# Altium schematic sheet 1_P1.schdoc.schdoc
size 309 x 223 mm; Symbol: Sheet-Symbol_A4; Device: Sheet-Symbol_A4; Company: A. ROMASZEWSKI; Drawed: EasyEDA Pro; Reviewed: EasyEDA Pro; Version: V0.1; Page Size: A4; @Project Name: stm32wb5mmg01; @Page Count: 1; @Update Date: 2023-12-18; @Create Date: 2023-10-27; @Schematic Name: Shield stm32wb5mm-dk; Part Number: SHMMDK-002; @Page No: 1; @Page Name: P1; attr-text: ADS1115 ADR I2C 0x76
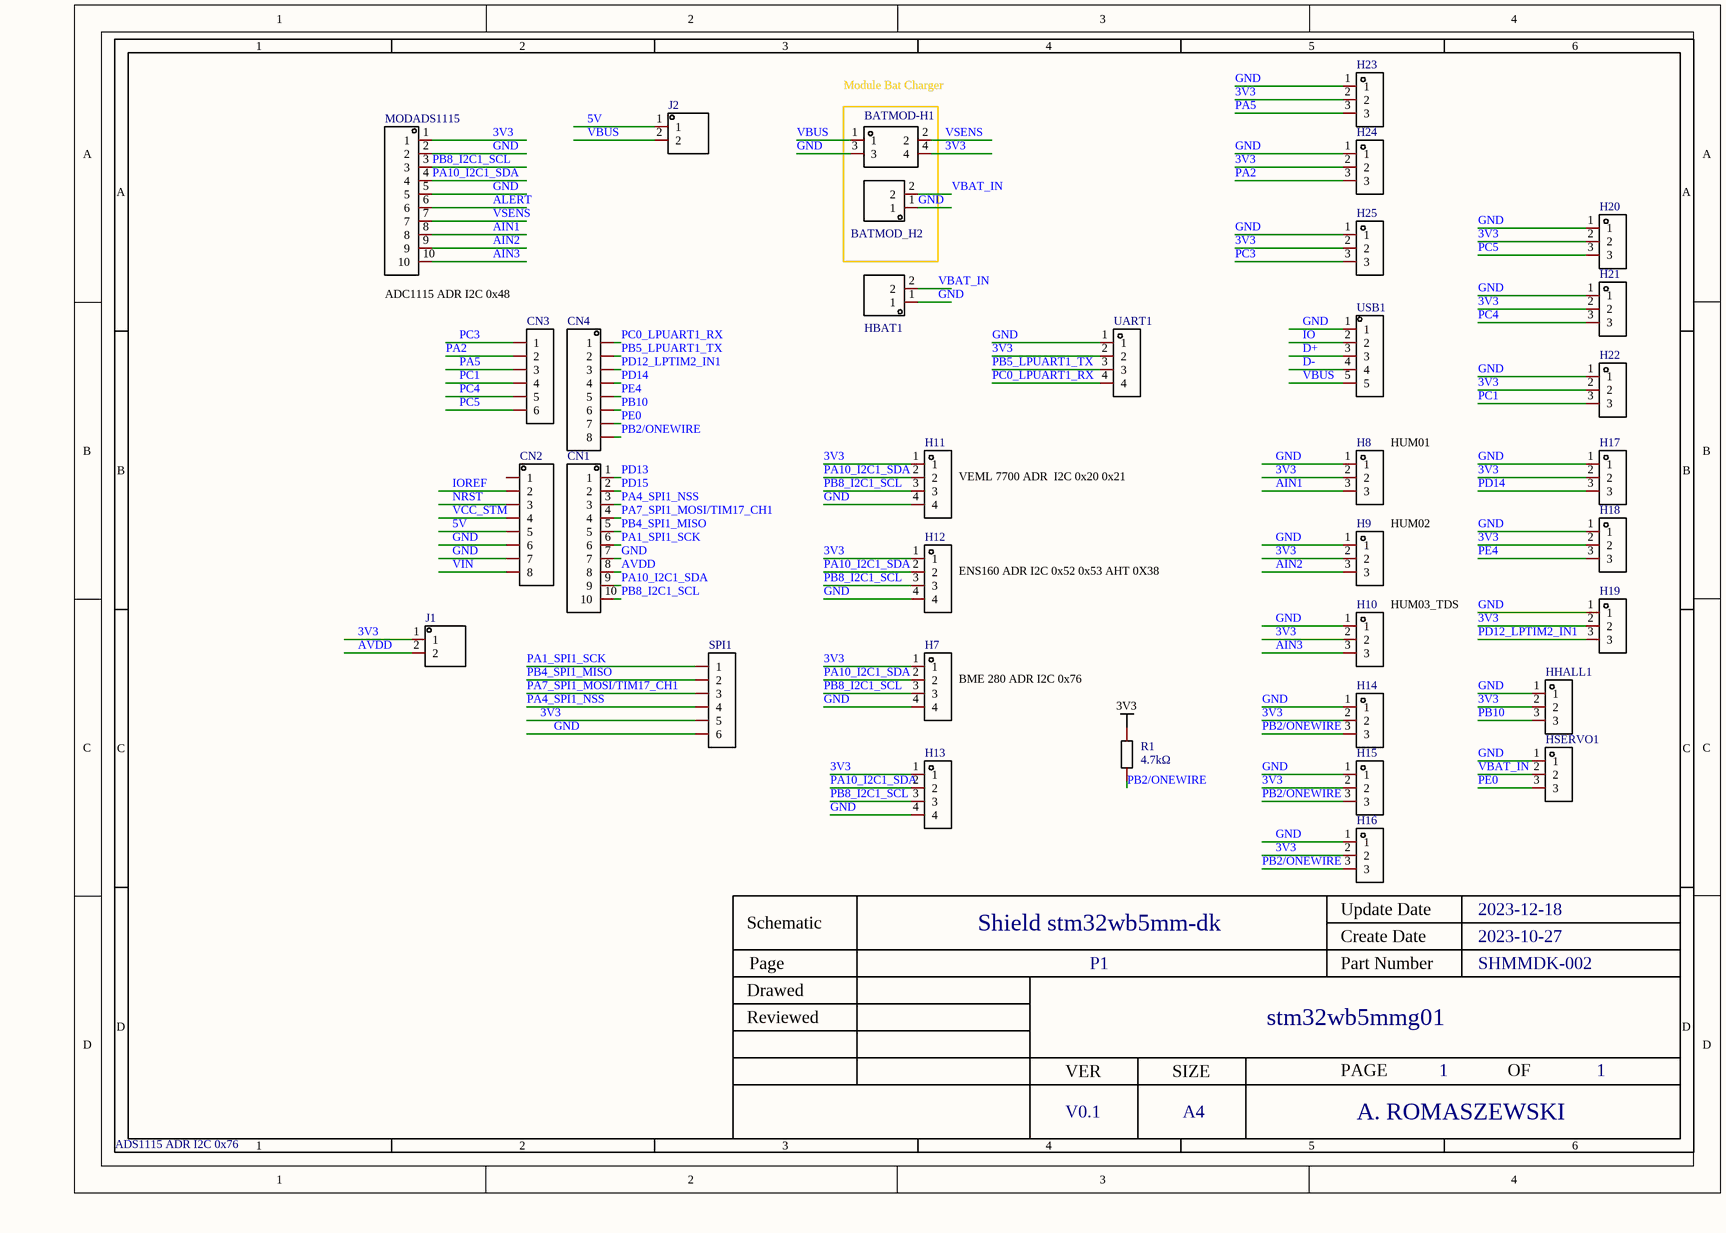
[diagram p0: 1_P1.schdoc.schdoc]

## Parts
BATMOD-H1  HDR-M_2.54_2x2  [HDR-TH_4P-P2.54-V-M-R2-C2-S2.54-1]  (value not drawn)
BATMOD_H2  HDR-M_2.54_1x2P  [HDR-TH_2P-P2.54-V-M-1]  (value not drawn)
CN1  HDR-M_2.54_1x10P  [HDR-TH_10P-P2.54-V-M-1]  (value not drawn)
CN2  HDR-M_2.54_1x8P  [HDR-TH_8P-P2.54-V-M]  (value not drawn)
CN3  HDR-M_2.54_1x6P  [HDR-TH_6P-P2.54-V-M-1]  (value not drawn)
CN4  HDR-M_2.54_1x8P  [HDR-TH_8P-P2.54-V-M]  (value not drawn)
H7  HDR-M_2.54_1x4P  [HDR-TH_4P-P2.54-V-M]  (value not drawn)
H8  HDR-M_2.54_1x3P  [HDR-TH_3P-P2.54-V-M]  (value not drawn)
H9  HDR-M_2.54_1x3P  [HDR-TH_3P-P2.54-V-M]  (value not drawn)
H10  HDR-M_2.54_1x3P  [HDR-TH_3P-P2.54-V-M]  (value not drawn)
H11  HDR-M_2.54_1x4P  [HDR-TH_4P-P2.54-V-M]  (value not drawn)
H12  HDR-M_2.54_1x4P  [HDR-TH_4P-P2.54-V-M]  (value not drawn)
H13  HDR-M_2.54_1x4P  [HDR-TH_4P-P2.54-V-M]  (value not drawn)
H14  HDR-M_2.54_1x3P  [HDR-TH_3P-P2.54-V-M]  (value not drawn)
H15  HDR-M_2.54_1x3P  [HDR-TH_3P-P2.54-V-M]  (value not drawn)
H16  HDR-M_2.54_1x3P  [HDR-TH_3P-P2.54-V-M]  (value not drawn)
H17  HDR-M_2.54_1x3P  [HDR-TH_3P-P2.54-V-M]  (value not drawn)
H18  HDR-M_2.54_1x3P  [HDR-TH_3P-P2.54-V-M]  (value not drawn)
H19  HDR-M_2.54_1x3P  [HDR-TH_3P-P2.54-V-M]  (value not drawn)
H20  HDR-M_2.54_1x3P  [HDR-TH_3P-P2.54-V-M]  (value not drawn)
H21  HDR-M_2.54_1x3P  [HDR-TH_3P-P2.54-V-M]  (value not drawn)
H22  HDR-M_2.54_1x3P  [HDR-TH_3P-P2.54-V-M]  (value not drawn)
H23  HDR-M_2.54_1x3P  [HDR-TH_3P-P2.54-V-M]  (value not drawn)
H24  HDR-M_2.54_1x3P  [HDR-TH_3P-P2.54-V-M]  (value not drawn)
H25  HDR-M_2.54_1x3P  [HDR-TH_3P-P2.54-V-M]  (value not drawn)
HBAT1  HDR-M_2.54_1x2P  [HDR-TH_2P-P2.54-V-M-1]  (value not drawn)
HHALL1  HDR-M_2.54_1x3P  [HDR-TH_3P-P2.54-V-M]  (value not drawn)
HSERVO1  HDR-M_2.54_1x3P  [HDR-TH_3P-P2.54-V-M]  (value not drawn)
J1  HDR-M_2.54_1x2P  [HDR-TH_2P-P2.54-V-M-1]  (value not drawn)
J2  HDR-M_2.54_1x2P  [HDR-TH_2P-P2.54-V-M-1]  (value not drawn)
MODADS1115  HDR-M_2.54_1x10P  [HDR-TH_10P-P2.54-V-M-1]  (value not drawn)
R1  4.7kΩ  [R1206]
SPI1  HDR-M_2.54_1x6P  [HDR-TH_6P-P2.54-V-M-1]  (value not drawn)
UART1  HDR-M_2.54_1x4P  [HDR-TH_4P-P2.54-V-M]  (value not drawn)
USB1  HDR-M_2.54_1x5P  [HDR-TH_5P-P2.54-V-M]  (value not drawn)

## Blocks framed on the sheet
Module Bat Charger: BATMOD-H1 BATMOD_H2

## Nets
3V3: BATMOD-H1.4 H7.1 H8.2 H9.2 H10.2 H11.1 H12.1 H13.1 H14.2 H15.2 H16.2 H17.2 H18.2 H19.2 H20.2 H21.2 H22.2 H23.2 H24.2 H25.2 HHALL1.2 J1.1 MODADS1115.1 R1.2 SPI1.5 UART1.2
5V: CN2.5 J2.1
AIN1: H8.3 MODADS1115.8
AIN2: H9.3 MODADS1115.9
AIN3: H10.3 MODADS1115.10
ALERT: MODADS1115.6
AVDD: CN1.8 J1.2
D+: USB1.3
D-: USB1.4
GND: BATMOD-H1.3 BATMOD_H2.1 CN1.7 CN2.6 CN2.7 H7.4 H8.1 H9.1 H10.1 H11.4 H12.4 H13.4 H14.1 H15.1 H16.1 H17.1 H18.1 H19.1 H20.1 H21.1 H22.1 H23.1 H24.1 H25.1 HBAT1.1 HHALL1.1 HSERVO1.1 MODADS1115.2 MODADS1115.5 SPI1.6 UART1.1 USB1.1
IO: USB1.2
IOREF: CN2.2
NRST: CN2.3
PA1_SPI1_SCK: CN1.6 SPI1.1
PA2: CN3.2 H24.3
PA4_SPI1_NSS: CN1.3 SPI1.4
PA5: CN3.3 H23.3
PA7_SPI1_MOSI/TIM17_CH1: CN1.4 SPI1.3
PA10_I2C1_SDA: CN1.9 H7.2 H11.2 H12.2 H13.2 MODADS1115.4
PB2/ONEWIRE: CN4.8 H14.3 H15.3 H16.3 R1.1
PB4_SPI1_MISO: CN1.5 SPI1.2
PB5_LPUART1_TX: CN4.2 UART1.3
PB8_I2C1_SCL: CN1.10 H7.3 H11.3 H12.3 H13.3 MODADS1115.3
PB10: CN4.6 HHALL1.3
PC0_LPUART1_RX: CN4.1 UART1.4
PC1: CN3.4 H22.3
PC3: CN3.1 H25.3
PC4: CN3.5 H21.3
PC5: CN3.6 H20.3
PD12_LPTIM2_IN1: CN4.3 H19.3
PD13: CN1.1
PD14: CN4.4 H17.3
PD15: CN1.2
PE0: CN4.7 HSERVO1.3
PE4: CN4.5 H18.3
VBAT_IN: BATMOD_H2.2 HBAT1.2 HSERVO1.2
VBUS: BATMOD-H1.1 J2.2 USB1.5
VCC_STM: CN2.4
VIN: CN2.8
VSENS: BATMOD-H1.2 MODADS1115.7

Not connected (* = marked no-connect by the designer): CN2 1

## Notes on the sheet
- (near MODADS1115) ADC1115 ADR I2C 0x48
- (near H8) HUM01
- (near H11) VEML 7700 ADR  I2C 0x20 0x21
- HUM02
- (near H12) ENS160 ADR I2C 0x52 0x53 AHT 0X38
- HUM03_TDS
- (near H7) BME 280 ADR I2C 0x76

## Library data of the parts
BATMOD-H1 = HDR-M_2.54_2x2: Symbol: HDR-M-2.54_2x2; Add into BOM: no; Convert to PCB: yes
BATMOD_H2 HBAT1 J1 J2 = HDR-M_2.54_1x2P: Symbol: 210S-1*2P L=11.6MMGold-plated black; Convert to PCB: yes; Add into BOM: no
CN1 MODADS1115 = HDR-M_2.54_1x10P: Symbol: Header-Male-2.54_1x10; Convert to PCB: yes; Add into BOM: no
CN2 CN4 = HDR-M_2.54_1x8P: Symbol: Header-Male-2.54_1x8; Convert to PCB: yes; Add into BOM: no
CN3 SPI1 = HDR-M_2.54_1x6P: Symbol: Header-Male-2.54_1x6; Convert to PCB: yes; Add into BOM: no
H7 H11-H13 UART1 = HDR-M_2.54_1x4P: Manufacturer: XFCN(兴飞); Symbol: PZ254V-11-04P; Convert to PCB: yes; Add into BOM: no
H8-H10 H14-H25 HHALL1 HSERVO1 = HDR-M_2.54_1x3P: Symbol: PZ254V-11-03P_C2937625; Convert to PCB: yes; Add into BOM: no
R1 = Res_1206: Symbol: Res; Add into BOM: no; Convert to PCB: yes
USB1 = HDR-M_2.54_1x5P: Symbol: MTP125-1105S1; Convert to PCB: yes; Add into BOM: no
